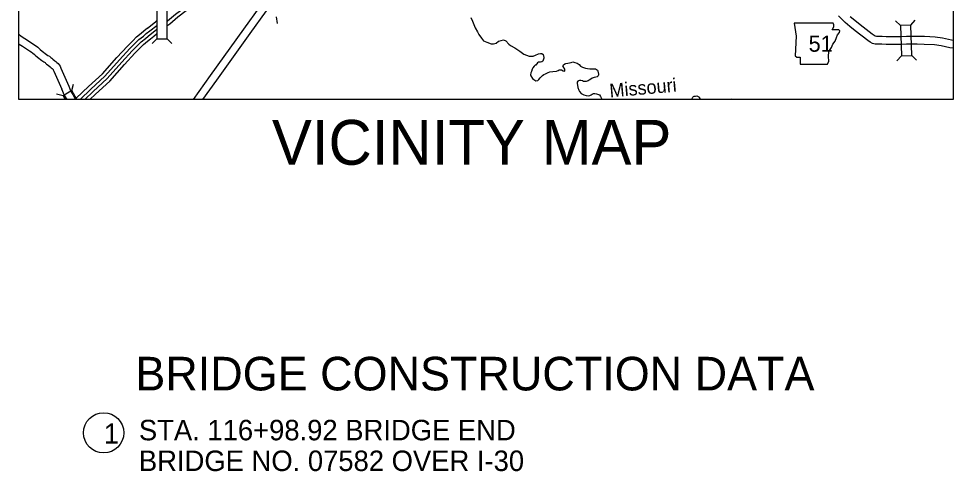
# Model space of a CAD drawing. Extents: x 8749 to 11879, y 13275 to 15339.
# Drawn here: x 8771 to 9501, y 14312 to 14666 of the extents above; entities that cross this region are included whole.
import ezdxf

# ---------------------------------------------------------------- set-up
doc = ezdxf.new("R2010")
doc.units = 0
for name, color, linetype in [('21', 7, 'Continuous'), ('Level 10', 7, 'Continuous'), ('Level 15', 7, 'Continuous'), ('Level 19', 7, 'Continuous'), ('Level 2', 7, 'Continuous'), ('Level 20', 7, 'Continuous'), ('Level 21', 7, 'Continuous'), ('Level 9', 7, 'Continuous'), ('R_Draft', 7, 'Continuous')]:
    doc.layers.add(name, color=color, linetype=linetype)

msp = doc.modelspace()

# ---------------------------------------------------------------- linework, layer by layer
at = {"layer": '21'}
msp.add_circle((8837.56, 14342.34), 15.74, dxfattribs=at)
at = {"layer": 'Level 10'}
for points in [[(9501.21, 14642.84), (9498.53, 14643.25), (9491.72, 14644.87), (9486.48, 14645.49), (9478.48, 14645.93), (9472.9, 14646.04), (9464.67, 14645.99), (9459.96, 14645.83), (9455.67, 14645.86), (9448.72, 14645.81), (9445.33, 14645.98), (9443.33, 14646), (9441.85, 14646.02), (9440.28, 14646.17), (9438.16, 14646.64), (9436.3, 14647.65), (9434.37, 14648.89), (9424.62, 14656.39), (9420.45, 14659.96), (9416.65, 14663.08), (9411.5, 14668.26)], [(9501.21, 14648.91), (9499.68, 14649.15), (9492.77, 14650.79), (9487, 14651.47), (9478.7, 14651.93), (9472.94, 14652.04), (9464.55, 14651.99), (9459.88, 14651.83), (9455.67, 14651.86), (9448.84, 14651.81), (9445.52, 14651.97), (9443.4, 14652), (9442.17, 14652.02), (9441.21, 14652.11), (9440.29, 14652.31), (9439.36, 14652.82), (9437.83, 14653.8), (9428.4, 14661.05), (9424.31, 14664.56), (9420.7, 14667.52)], [(8771.23, 14653.76), (8771.59, 14653.52), (8772.82, 14652.46), (8774.75, 14651.22), (8777.42, 14649.62), (8783, 14645.89), (8784.43, 14644.95), (8786.11, 14643.74), (8787.34, 14642.61), (8788.07, 14641.94), (8789.69, 14640.65), (8793.01, 14638.05), (8794.04, 14637.31), (8795.29, 14636.63), (8796.32, 14635.72), (8797.06, 14635.03), (8797.97, 14634.26), (8799.53, 14632.98), (8800.15, 14632.5), (8801.11, 14631.83), (8802.07, 14631.05), (8802.88, 14629.96), (8803.52, 14628.8), (8804.18, 14627.38), (8810.31, 14613.36)], [(8771.23, 14646.35), (8771.59, 14646.12), (8774.21, 14644.55), (8779.68, 14640.89), (8781.02, 14640.01), (8782.32, 14639.08), (8783.29, 14638.18), (8784.17, 14637.38), (8785.97, 14635.94), (8789.4, 14633.26), (8790.83, 14632.22), (8791.83, 14631.68), (8792.28, 14631.28), (8793.07, 14630.54), (8794.13, 14629.64), (8795.78, 14628.3), (8796.58, 14627.67), (8797.5, 14627.03), (8797.71, 14626.86), (8797.82, 14626.71), (8798.16, 14626.09), (8798.71, 14624.91), (8804.81, 14610.96)], [(8804.77, 14611.07), (8806.63, 14606.28), (8808.33, 14603.5), (8808.71, 14602.87)], [(8810.36, 14613.25), (8812.03, 14608.95), (8813.45, 14606.63), (8815.42, 14603.4), (8815.68, 14602.87)]]:
    msp.add_lwpolyline(points, dxfattribs=at)
at = {"layer": 'Level 15'}
for points in [[(8907.81, 14602.87), (8921.05, 14621.45), (8947.08, 14657.8), (8972.67, 14693.47), (8988.96, 14716.39), (8999.9, 14731.87), (9003.89, 14737.5), (9007.02, 14741.88), (9008.71, 14743.96), (9009.42, 14745.09), (9010.95, 14746.66), (9011.98, 14747.67), (9013.58, 14749.11), (9015.15, 14750.23), (9017.12, 14751.64), (9020.65, 14753.18), (9025.2, 14754.54), (9050.18, 14762.92)], [(8915.18, 14602.87), (8925.93, 14617.96), (8951.96, 14654.31), (8977.56, 14689.98), (8993.86, 14712.92), (9004.8, 14728.41), (9008.78, 14734.02), (9011.79, 14738.24), (9013.59, 14740.45), (9014.16, 14741.36), (9015.2, 14742.43), (9016.09, 14743.3), (9017.33, 14744.42), (9018.64, 14745.34), (9020.11, 14746.4), (9022.71, 14747.54), (9027.01, 14748.81), (9052.09, 14757.23)]]:
    msp.add_lwpolyline(points, dxfattribs=at)
at = {"layer": 'Level 19'}
for points in [[(8886.96, 14663.81), (8887.45, 14664.18), (8893.81, 14669.48), (8900.4, 14674.48), (8907.13, 14680.22), (8918.13, 14688.66), (8927.03, 14696.5), (8933.12, 14702.14), (8957.25, 14724.2), (8994.98, 14758.42)], [(8886.97, 14660.33), (8889.17, 14662.04), (8895.52, 14667.32), (8902.13, 14672.34), (8908.86, 14678.08), (8919.88, 14686.54), (8928.87, 14694.46), (8934.99, 14700.12), (8959.1, 14722.16), (8996.82, 14756.38)], [(8816.08, 14603.77), (8825.77, 14612.9), (8836.6, 14622.9), (8847.98, 14635.64), (8856.11, 14644.6), (8860.31, 14648.76), (8863.3, 14651.84), (8866.83, 14654.55), (8868.98, 14656.47), (8871.92, 14658.73)], [(8871.89, 14658.7), (8878.06, 14663.53), (8878.99, 14664.26)], [(8873.58, 14656.54), (8879.01, 14660.78)], [(8819.13, 14602.87), (8827.65, 14610.89), (8838.57, 14620.96), (8850.03, 14633.8), (8858.1, 14642.69), (8862.26, 14646.82), (8865.14, 14649.78), (8868.59, 14652.44), (8870.73, 14654.36), (8873.59, 14656.55)], [(8822.78, 14602.87), (8829.35, 14609.06), (8840.35, 14619.21), (8851.88, 14632.13), (8859.91, 14640.96), (8864.04, 14645.06), (8866.8, 14647.91), (8870.19, 14650.51), (8872.33, 14652.43), (8875.11, 14654.56)], [(8826.79, 14602.87), (8831.23, 14607.05), (8842.31, 14617.28), (8853.93, 14630.29), (8861.9, 14639.06), (8866, 14643.13), (8868.64, 14645.85), (8871.94, 14648.39), (8874.09, 14650.31), (8876.79, 14652.38)], [(8875.13, 14654.57), (8878.88, 14657.51)], [(8876.82, 14652.41), (8878.92, 14654.05)]]:
    msp.add_lwpolyline(points, dxfattribs=at)
at = {"layer": 'Level 2'}
for points in [[(9124.26, 14666.88), (9125.57, 14664.01), (9126.65, 14661.43), (9127.7, 14658.76), (9129.5, 14655.68), (9130.64, 14653.69), (9132.59, 14650.85), (9134.21, 14648.76), (9136.77, 14647.54), (9140.22, 14646.37), (9142.12, 14646.21), (9144.12, 14646.78), (9146.09, 14648.3), (9148.03, 14648.98), (9149.89, 14649.4), (9151.79, 14648.8), (9154.02, 14646.17), (9155.44, 14644.92), (9158.7, 14643.28), (9162.63, 14640.61), (9165.67, 14638.32), (9169.93, 14636.77), (9172.96, 14636.69), (9174.97, 14637.47), (9177.27, 14638.56), (9178.69, 14638.88), (9179.91, 14638.78), (9180.77, 14637.98), (9181.18, 14637.04), (9181.32, 14635.62), (9181.36, 14635.07), (9180.54, 14632.75), (9179.9, 14632.23), (9178.9, 14631.89), (9177.8, 14632.04), (9177.1, 14632), (9176.42, 14631.58), (9175.88, 14630.8), (9175.69, 14630.34), (9175.13, 14629.76), (9174.57, 14629.54), (9173.71, 14628.96), (9172.75, 14627.66), (9172.31, 14626.56), (9171.75, 14624.65), (9171.18, 14623.63), (9171.02, 14622.17), (9171.16, 14621.19), (9172.66, 14619.17), (9173.54, 14618.44), (9175.13, 14617.54), (9176.61, 14617.76), (9177.54, 14618.4), (9178.56, 14619.82), (9180.3, 14621.58), (9181.32, 14622.46)], [(9124.26, 14666.88), (9125.57, 14664.01), (9126.65, 14661.43), (9127.7, 14658.76), (9129.5, 14655.68), (9130.64, 14653.69), (9132.59, 14650.85), (9134.21, 14648.76), (9136.77, 14647.54), (9140.22, 14646.37), (9142.12, 14646.21), (9144.12, 14646.78), (9146.09, 14648.3), (9148.03, 14648.98), (9149.89, 14649.4), (9151.79, 14648.8), (9154.02, 14646.17), (9155.44, 14644.92), (9158.7, 14643.28), (9162.63, 14640.61), (9165.67, 14638.32), (9169.93, 14636.77), (9172.96, 14636.69), (9174.97, 14637.47), (9177.27, 14638.56), (9178.69, 14638.88), (9179.91, 14638.78), (9180.77, 14637.98), (9181.18, 14637.04), (9181.32, 14635.62), (9181.36, 14635.07), (9180.54, 14632.75), (9179.9, 14632.23), (9178.9, 14631.89), (9177.8, 14632.04), (9177.1, 14632), (9176.42, 14631.58), (9175.88, 14630.8), (9175.69, 14630.34), (9175.13, 14629.76), (9174.57, 14629.54), (9173.71, 14628.96), (9172.75, 14627.66), (9172.31, 14626.56), (9171.75, 14624.65), (9171.18, 14623.63), (9171.02, 14622.17), (9171.16, 14621.19), (9172.66, 14619.17), (9173.54, 14618.44), (9175.13, 14617.54), (9176.61, 14617.76), (9177.54, 14618.4), (9178.56, 14619.82), (9180.3, 14621.58), (9181.32, 14622.46)], [(9181.32, 14622.46), (9182.66, 14623), (9184.86, 14623.89), (9185.98, 14624.45), (9188.34, 14624.69), (9191.2, 14625.05), (9192.6, 14625.53), (9193.45, 14625.9), (9194.23, 14626.02), (9195.31, 14625.88), (9196.6, 14625.22), (9197.56, 14625.02), (9197.84, 14625.24), (9197.92, 14625.78), (9197.67, 14626.64), (9196.49, 14628.5), (9196.33, 14629), (9196.49, 14629.36), (9196.77, 14629.89), (9197.73, 14630.74), (9198.57, 14631.02), (9200.07, 14631.16), (9201.37, 14631.36), (9202.73, 14631.8), (9204.09, 14632.26), (9205.73, 14631.69), (9207.33, 14631.21), (9208.95, 14630.17), (9210.15, 14629), (9211.69, 14628.1), (9213.81, 14627.32), (9215.5, 14626.97), (9217.28, 14626.89), (9218.68, 14626.77), (9219.94, 14626.77), (9220.88, 14626.85), (9221.74, 14626.81), (9222.58, 14626.2), (9223.18, 14625.76), (9223.64, 14624.96), (9224.18, 14622.52), (9224.12, 14621.98), (9223.89, 14621.37), (9223.69, 14621.01), (9223.05, 14620.49), (9222.05, 14620.34), (9220.81, 14620), (9219.11, 14619.42), (9218.19, 14618.78), (9216.89, 14618.04), (9215.93, 14617.54), (9214.33, 14616.92), (9213.41, 14616.9), (9212.47, 14616.93), (9211.51, 14617.39), (9210.17, 14617.71), (9209.21, 14617.79), (9208.49, 14617.53), (9207.97, 14617.13), (9207.55, 14616.29), (9207.55, 14615.27), (9207.67, 14613.91), (9208.02, 14612.1), (9208.84, 14610.02), (9209.24, 14609.04), (9210.61, 14607.6), (9212.51, 14606.55), (9214.51, 14606.03), (9215.95, 14605.72), (9217.37, 14605.88), (9218.49, 14606.4), (9219.21, 14606.88), (9220.19, 14607.58), (9221.29, 14607.58), (9222.55, 14607.2), (9224.09, 14606.75), (9224.85, 14606.41), (9225.75, 14605.25), (9226.39, 14603.69), (9226.53, 14602.87)], [(9181.32, 14622.46), (9182.66, 14623), (9184.86, 14623.89), (9185.98, 14624.45), (9188.34, 14624.69), (9191.2, 14625.05), (9192.6, 14625.53), (9193.45, 14625.9), (9194.23, 14626.02), (9195.31, 14625.88), (9196.6, 14625.22), (9197.56, 14625.02), (9197.84, 14625.24), (9197.92, 14625.78), (9197.67, 14626.64), (9196.49, 14628.5), (9196.33, 14629), (9196.49, 14629.36), (9196.77, 14629.89), (9197.73, 14630.74), (9198.57, 14631.02), (9200.07, 14631.16), (9201.37, 14631.36), (9202.73, 14631.8), (9204.09, 14632.26), (9205.73, 14631.69), (9207.33, 14631.21), (9208.95, 14630.17), (9210.15, 14629), (9211.69, 14628.1), (9213.81, 14627.32), (9215.5, 14626.97), (9217.28, 14626.89), (9218.68, 14626.77), (9219.94, 14626.77), (9220.88, 14626.85), (9221.74, 14626.81), (9222.58, 14626.2), (9223.18, 14625.76), (9223.64, 14624.96), (9224.18, 14622.52), (9224.12, 14621.98), (9223.89, 14621.37), (9223.69, 14621.01), (9223.05, 14620.49), (9222.05, 14620.34), (9220.81, 14620), (9219.11, 14619.42), (9218.19, 14618.78), (9216.89, 14618.04), (9215.93, 14617.54), (9214.33, 14616.92), (9213.41, 14616.9), (9212.47, 14616.93), (9211.51, 14617.39), (9210.17, 14617.71), (9209.21, 14617.79), (9208.49, 14617.53), (9207.97, 14617.13), (9207.55, 14616.29), (9207.55, 14615.27), (9207.67, 14613.91), (9208.02, 14612.1), (9208.84, 14610.02), (9209.24, 14609.04), (9210.61, 14607.6), (9212.51, 14606.55), (9214.51, 14606.03), (9215.95, 14605.72), (9217.37, 14605.88), (9218.49, 14606.4), (9219.21, 14606.88), (9220.19, 14607.58), (9221.29, 14607.58), (9222.55, 14607.2), (9224.09, 14606.75), (9224.85, 14606.41), (9225.75, 14605.25), (9226.39, 14603.69), (9226.53, 14602.87)], [(9297.09, 14602.87), (9297.1, 14602.9), (9297.37, 14603.62), (9297.74, 14604.56), (9298.19, 14605.07), (9298.87, 14605.44), (9299.97, 14605.51), (9300.8, 14605.64), (9301.96, 14605.29), (9302.39, 14604.91), (9302.81, 14604.34), (9303.2, 14603.66), (9303.31, 14602.87)], [(9297.09, 14602.87), (9297.1, 14602.9), (9297.37, 14603.62), (9297.74, 14604.56), (9298.19, 14605.07), (9298.87, 14605.44), (9299.97, 14605.51), (9300.8, 14605.64), (9301.96, 14605.29), (9302.39, 14604.91), (9302.81, 14604.34), (9303.2, 14603.66), (9303.31, 14602.87)], [(9326.31, 14602.87), (9326.61, 14603.06), (9328.22, 14603.24), (9328.58, 14602.87)], [(9326.31, 14602.87), (9326.61, 14603.06), (9328.22, 14603.24), (9328.58, 14602.87)]]:
    msp.add_lwpolyline(points, dxfattribs=at)
at = {"layer": 'Level 20'}
for p, q in [((8972.25, 14667.35), (8973.1, 14662.14)), ((9460.02, 14660.72), (9456.16, 14664.33)), ((9467.94, 14660.98), (9471.54, 14664.84)), ((8879.19, 14650.23), (8875.44, 14646.5)), ((8887.11, 14650.21), (8890.83, 14646.46)), ((9460.81, 14636.97), (9457.2, 14633.12)), ((9468.73, 14637.24), (9472.58, 14633.63)), ((8812.72, 14609.75), (8814.06, 14614.86)), ((8805.88, 14605.76), (8800.78, 14607.1))]:
    msp.add_line(p, q, dxfattribs=at)
for points in [[(8887.11, 14650.21), (8887.17, 14673.97), (8879.25, 14673.99), (8879.19, 14650.23)], [(9460.02, 14660.72), (9460.81, 14636.97), (9468.73, 14637.24), (9467.94, 14660.98)]]:
    msp.add_lwpolyline(points, close=True, dxfattribs=at)
msp.add_lwpolyline([(8816.74, 14602.87), (8812.72, 14609.75), (8805.88, 14605.76), (8807.57, 14602.87)], dxfattribs=at)
at = {"layer": 'Level 21'}
msp.add_lwpolyline([(9376.88, 14662.37), (9378.4, 14652.22), (9377.72, 14636.82), (9379.07, 14635.97), (9381.61, 14635.97), (9381.61, 14630.56), (9402.93, 14630.56), (9403.94, 14632.76), (9403.61, 14636.31), (9404.11, 14640.37), (9405.97, 14643.59), (9407.16, 14645.96), (9408.85, 14648.49), (9409.87, 14651.2), (9410.71, 14653.4), (9412.23, 14655.26), (9412.57, 14656.45), (9411.9, 14657.29), (9406.65, 14657.29), (9407.84, 14659.66), (9408, 14661.18), (9407.3, 14662.35)], close=True, dxfattribs=at)
at = {"layer": 'R_Draft'}
msp.add_lwpolyline([(8771.23, 15238.52), (9501.21, 15238.52), (9501.21, 14602.87), (8771.23, 14602.87)], close=True, dxfattribs=at)

# ---------------------------------------------------------------- texts
at = {"layer": '21'}
for s, height, p in [('BRIDGE CONSTRUCTION DATA', 26.25, (8862.33, 14375.47)), ('STA. 116+98.92 BRIDGE END ', 16, (8865.13, 14336.47)), ('1', 15.85, (8837.75, 14333.84)), ('BRIDGE NO. 07582 OVER I-30', 16, (8865.13, 14312.47))]:
    msp.add_text(s, height=height, dxfattribs=at).set_placement(p)
at = {"layer": 'Level 21'}
msp.add_text('51', height=12.672, dxfattribs=at).set_placement((9388.2, 14640.15))
at = {"layer": 'Level 9'}
msp.add_text('Missouri', height=10.56, rotation=5, dxfattribs=at).set_placement((9233.08, 14604.45))
at = {"layer": 'R_Draft'}
msp.add_text('VICINITY MAP', height=35, dxfattribs=at).set_placement((8969, 14551.84))

doc.saveas('drawing.dxf')
